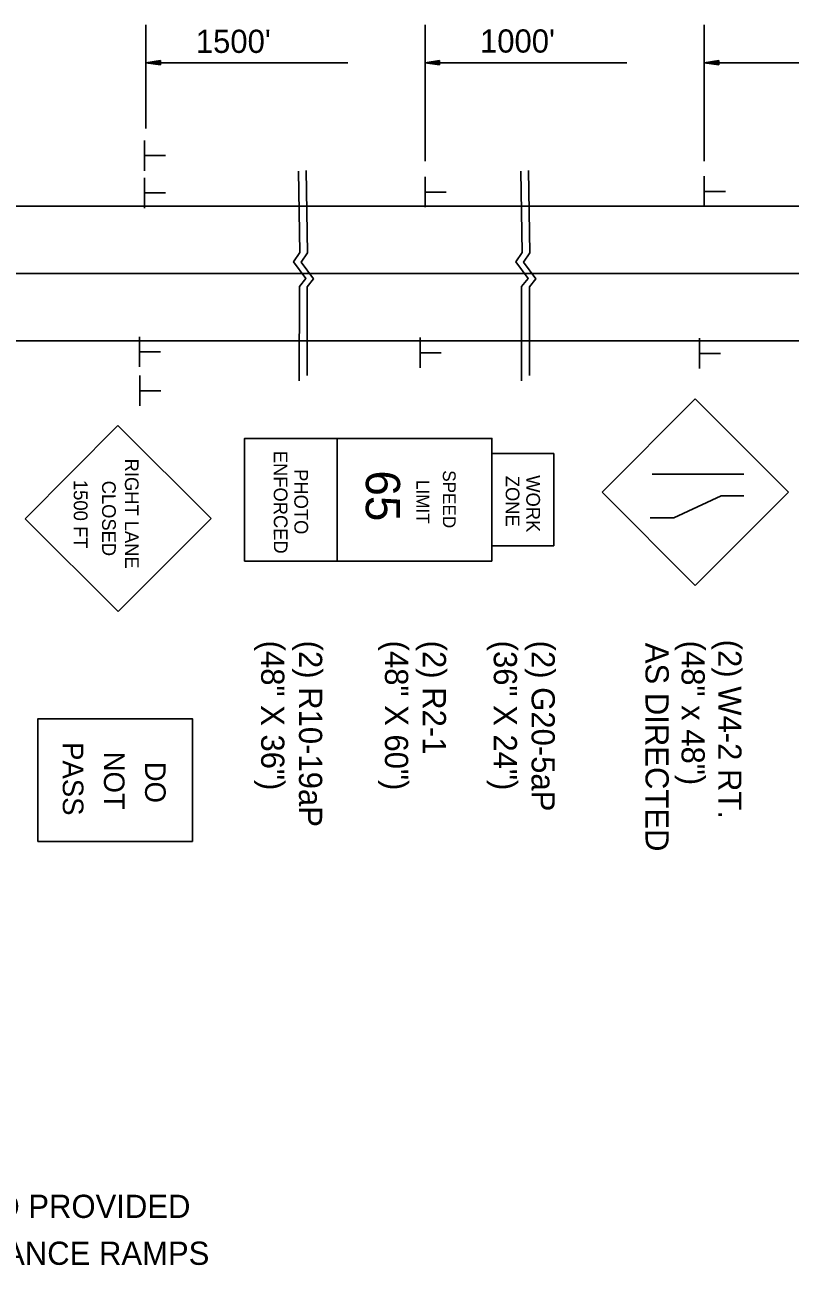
# Model space of a CAD drawing. Extents: x 1374027 to 1374537, y 380415 to 381405.
# Drawn here: x 1374086.06 to 1374105.84, y 380906.54 to 380938.61 of the extents above; entities that cross this region are included whole.
import ezdxf

# ---------------------------------------------------------------- set-up
doc = ezdxf.new("R2010")
doc.units = 0
doc.layers.add('Default', color=7, linetype='Continuous')

msp = doc.modelspace()

# ---------------------------------------------------------------- linework, layer by layer
at = {"layer": 'Default'}
for p, q in [((1374089.184, 380938.607), (1374089.184, 380935.922)), ((1374096.4, 380938.607), (1374096.4, 380935.086)), ((1374103.617, 380938.607), (1374103.617, 380935.086)), ((1374089.559, 380937.684), (1374089.184, 380937.627)), ((1374089.184, 380937.627), (1374094.403, 380937.627)), ((1374089.559, 380937.571), (1374089.184, 380937.627)), ((1374089.559, 380937.674), (1374089.246, 380937.627)), ((1374089.559, 380937.581), (1374089.246, 380937.627)), ((1374089.559, 380937.665), (1374089.311, 380937.627)), ((1374089.559, 380937.59), (1374089.311, 380937.627)), ((1374089.559, 380937.655), (1374089.373, 380937.627)), ((1374089.559, 380937.6), (1374089.373, 380937.627)), ((1374089.559, 380937.646), (1374089.437, 380937.627)), ((1374089.559, 380937.609), (1374089.437, 380937.627)), ((1374089.559, 380937.636), (1374089.5, 380937.627)), ((1374089.559, 380937.619), (1374089.5, 380937.627)), ((1374089.559, 380937.571), (1374089.559, 380937.684)), ((1374096.775, 380937.684), (1374096.4, 380937.627)), ((1374096.4, 380937.627), (1374101.619, 380937.627)), ((1374096.775, 380937.571), (1374096.4, 380937.627)), ((1374096.775, 380937.674), (1374096.463, 380937.627)), ((1374096.775, 380937.581), (1374096.463, 380937.627)), ((1374096.775, 380937.665), (1374096.527, 380937.627)), ((1374096.775, 380937.59), (1374096.527, 380937.627)), ((1374096.775, 380937.655), (1374096.59, 380937.627)), ((1374096.775, 380937.6), (1374096.59, 380937.627)), ((1374096.775, 380937.646), (1374096.653, 380937.627)), ((1374096.775, 380937.609), (1374096.653, 380937.627)), ((1374096.775, 380937.636), (1374096.716, 380937.627)), ((1374096.775, 380937.619), (1374096.716, 380937.627)), ((1374096.775, 380937.571), (1374096.775, 380937.684)), ((1374103.992, 380937.684), (1374103.617, 380937.627)), ((1374103.617, 380937.627), (1374110.164, 380937.627)), ((1374103.992, 380937.571), (1374103.617, 380937.627)), ((1374103.992, 380937.674), (1374103.679, 380937.627)), ((1374103.992, 380937.581), (1374103.679, 380937.627)), ((1374103.992, 380937.665), (1374103.744, 380937.627)), ((1374103.992, 380937.59), (1374103.744, 380937.627)), ((1374103.992, 380937.655), (1374103.806, 380937.627)), ((1374103.992, 380937.6), (1374103.806, 380937.627)), ((1374103.992, 380937.646), (1374103.87, 380937.627)), ((1374103.992, 380937.609), (1374103.87, 380937.627)), ((1374103.992, 380937.636), (1374103.933, 380937.627)), ((1374103.992, 380937.619), (1374103.933, 380937.627)), ((1374103.992, 380937.571), (1374103.992, 380937.684)), ((1374089.147, 380934.835), (1374089.147, 380935.618)), ((1374089.159, 380935.224), (1374089.693, 380935.224)), ((1374089.145, 380933.87), (1374089.145, 380934.652)), ((1374096.4, 380933.891), (1374096.4, 380934.673)), ((1374103.617, 380933.912), (1374103.617, 380934.694)), ((1374089.157, 380934.259), (1374089.691, 380934.259)), ((1374096.412, 380934.28), (1374096.946, 380934.28)), ((1374103.628, 380934.301), (1374104.162, 380934.301)), ((1374039.716, 380933.916), (1374181.443, 380933.916)), ((1374039.716, 380932.177), (1374181.443, 380932.177)), ((1374039.716, 380930.439), (1374181.443, 380930.439)), ((1374089.019, 380929.763), (1374089.019, 380930.545)), ((1374096.274, 380929.742), (1374096.274, 380930.524)), ((1374103.49, 380929.721), (1374103.49, 380930.503)), ((1374089.031, 380930.152), (1374089.565, 380930.152)), ((1374096.286, 380930.131), (1374096.82, 380930.131)), ((1374103.502, 380930.11), (1374104.036, 380930.11)), ((1374089.028, 380928.758), (1374089.028, 380929.54)), ((1374089.039, 380929.147), (1374089.574, 380929.147)), ((1374103.384, 380928.935), (1374100.975, 380926.526)), ((1374103.384, 380928.935), (1374105.794, 380926.526)), ((1374086.061, 380925.839), (1374088.462, 380928.249)), ((1374090.87, 380925.847), (1374088.462, 380928.249)), ((1374102.268, 380926.989), (1374104.638, 380926.989)), ((1374100.975, 380926.526), (1374103.384, 380924.116)), ((1374102.83, 380925.865), (1374104.055, 380926.427)), ((1374105.794, 380926.526), (1374103.384, 380924.116)), ((1374104.055, 380926.427), (1374104.638, 380926.427)), ((1374088.471, 380923.437), (1374086.061, 380925.839)), ((1374088.471, 380923.437), (1374090.87, 380925.847)), ((1374102.217, 380925.865), (1374102.83, 380925.865))]:
    msp.add_line(p, q, dxfattribs=at)
for points in [[(1374093.131, 380934.823), (1374093.163, 380932.72), (1374093.001, 380932.478), (1374093.317, 380932.045), (1374093.151, 380931.846), (1374093.15, 380929.4)], [(1374093.331, 380934.842), (1374093.363, 380932.711), (1374093.201, 380932.47), (1374093.517, 380932.037), (1374093.35, 380931.837), (1374093.35, 380929.54)], [(1374098.877, 380934.823), (1374098.909, 380932.72), (1374098.747, 380932.478), (1374099.063, 380932.045), (1374098.897, 380931.846), (1374098.896, 380929.4)], [(1374099.076, 380934.842), (1374099.109, 380932.711), (1374098.946, 380932.47), (1374099.263, 380932.037), (1374099.096, 380931.837), (1374099.096, 380929.54)]]:
    msp.add_lwpolyline(points, dxfattribs=at)
for points in [[(1374094.132, 380924.746), (1374091.734, 380924.746), (1374091.734, 380927.917), (1374094.132, 380927.917)], [(1374098.129, 380924.746), (1374094.132, 380924.746), (1374094.132, 380927.917), (1374098.129, 380927.917)], [(1374099.728, 380925.142), (1374098.129, 380925.142), (1374098.129, 380927.521), (1374099.728, 380927.521)], [(1374090.389, 380917.499), (1374086.392, 380917.499), (1374086.392, 380920.67), (1374090.389, 380920.67)]]:
    msp.add_lwpolyline(points, close=True, dxfattribs=at)

# ---------------------------------------------------------------- texts
for s, p in [("1500'", (1374090.475, 380937.88)), ("1000'", (1374097.82, 380937.888)), ('SPEED LIMIT SIGNS ARE ALSO PROVIDED', (1374073.974, 380907.765)), ('FOR PLACEMENT PAST ENTRANCE RAMPS ', (1374073.974, 380906.552))]:
    msp.add_text(s, height=0.6, dxfattribs=at).set_placement(p)
for s, height, rotation, p in [('RIGHT LANE', 0.3544, 270.1004, (1374088.641, 380927.392)), ('ENFORCED', 0.3544, 270.1004, (1374092.488, 380927.594)), ('PHOTO', 0.3544, 270.1004, (1374093.02, 380927.12)), ('65', 0.8852, 270, (1374094.869, 380927.088)), ('SPEED', 0.3303, 270, (1374096.861, 380927.092)), ('1500 FT', 0.3567, 270.0006, (1374087.32, 380926.844)), ('CLOSED', 0.3543, 270.1003, (1374088.051, 380926.821)), ('LIMIT', 0.3303, 270, (1374096.179, 380926.839)), ('ZONE', 0.3544, 270.1004, (1374098.484, 380926.948)), ('WORK', 0.3544, 270.1004, (1374099.016, 380926.963)), ('(48" X 36")', 0.6, 270, (1374092.164, 380922.688)), ('(2) R10-19aP', 0.6, 270, (1374093.142, 380922.688)), ('(48" X 60")', 0.6, 270, (1374095.364, 380922.688)), ('(2) R2-1', 0.6, 270, (1374096.342, 380922.688)), ('(36" X 24")', 0.6, 270, (1374098.176, 380922.688)), ('(2) G20-5aP', 0.6, 270, (1374099.154, 380922.688)), ('AS DIRECTED ', 0.6, 270, (1374102.098, 380922.632)), ('(48" x 48")', 0.6, 270, (1374103.03, 380922.688)), ('(2) W4-2 RT.', 0.6, 270, (1374103.979, 380922.713)), ('PASS', 0.5319, 270, (1374087.037, 380920.065)), ('NOT', 0.532, 270, (1374088.101, 380919.818)), ('DO', 0.532, 270, (1374089.164, 380919.558))]:
    msp.add_text(s, height=height, rotation=rotation, dxfattribs=at).set_placement(p)

doc.saveas('drawing.dxf')
